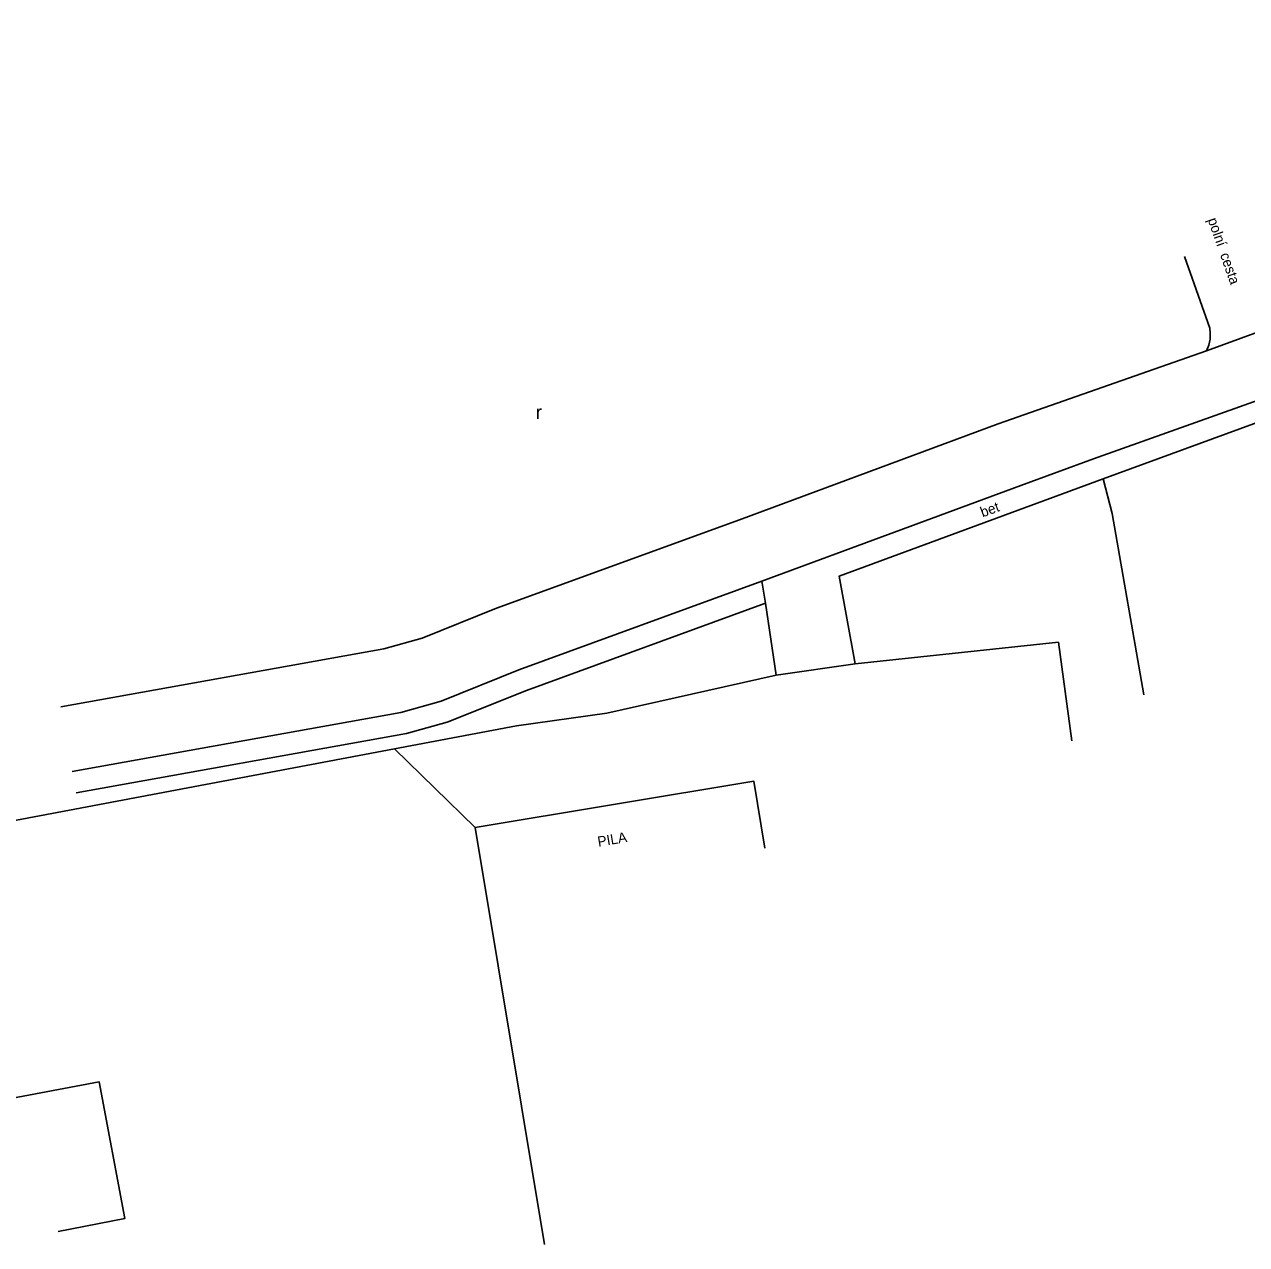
# Model space of a CAD drawing. Extents: x -544674 to -541478, y -1199076 to -1195527.
# Drawn here: x -542696.6 to -542606.7, y -1198958.2 to -1198868.4 of the extents above; entities that cross this region are included whole.
import ezdxf

# ---------------------------------------------------------------- set-up
doc = ezdxf.new("R2010")
doc.units = 0
for name, color, linetype in [('BUDOVY_MĚŘ', 7, 'Continuous'), ('POMOC_POPIS', 7, 'Continuous'), ('ROZHRANÍ_PLOCH', 7, 'Continuous'), ('ZN_DOPLŇKOVÉ', 7, 'Continuous'), ('ZN_KULTUR', 7, 'Continuous')]:
    doc.layers.add(name, color=color, linetype=linetype)

msp = doc.modelspace()

# ---------------------------------------------------------------- linework, layer by layer
at = {"layer": 'BUDOVY_MĚŘ'}
for points in [[(-542663.42, -1198927.53), (-542642.92, -1198924.11), (-542642.1, -1198929.04)], [(-542658.32, -1198958.2), (-542663.42, -1198927.53)], [(-542694.09, -1198957.23), (-542689.18, -1198956.28), (-542691.07, -1198946.23), (-542716.46, -1198951), (-542715.54, -1198955.91)]]:
    msp.add_lwpolyline(points, dxfattribs=at)
at = {"layer": 'ROZHRANÍ_PLOCH'}
for points in [[(-542527.8, -1198868.44), (-542528.3, -1198868.51), (-542529.54, -1198868.77), (-542530.76, -1198869.11), (-542531.26, -1198869.27), (-542565.34, -1198881.65), (-542617.93, -1198900.4), (-542623.29, -1198902.35), (-542642.32, -1198909.4)], [(-542611.23, -1198885.52), (-542609.38, -1198890.79), (-542609.34, -1198891.15), (-542609.36, -1198891.6), (-542609.45, -1198892.04), (-542609.63, -1198892.45)], [(-542609.63, -1198892.45), (-542601.96, -1198889.66)], [(-542693.91, -1198918.65), (-542670.14, -1198914.38), (-542667.32, -1198913.6), (-542661.84, -1198911.39), (-542643.98, -1198904.88), (-542624.95, -1198897.83), (-542609.63, -1198892.45)], [(-542617.21, -1198901.86), (-542636.64, -1198909.02), (-542635.46, -1198915.48)], [(-542642.32, -1198909.4), (-542660.2, -1198915.92), (-542665.93, -1198918.23), (-542668.89, -1198919.05), (-542693.06, -1198923.39)], [(-542642.07, -1198911.02), (-542642.32, -1198909.4)], [(-542642.07, -1198911.02), (-542659.65, -1198917.43), (-542665.47, -1198919.78), (-542668.47, -1198920.61), (-542692.78, -1198924.97)], [(-542641.27, -1198916.32), (-542642.07, -1198911.02)]]:
    msp.add_lwpolyline(points, dxfattribs=at)
at = {"layer": 'ZN_DOPLŇKOVÉ'}
for points in [[(-542617.21, -1198901.86), (-542601.14, -1198895.99), (-542585.1, -1198890.32), (-542564.95, -1198883.27)], [(-542617.21, -1198901.86), (-542616.56, -1198904.41)], [(-542614.24, -1198917.75), (-542616.56, -1198904.41)], [(-542635.46, -1198915.48), (-542620.51, -1198913.89), (-542619.52, -1198921.15)], [(-542635.46, -1198915.48), (-542641.27, -1198916.32)], [(-542669.35, -1198921.73), (-542660.39, -1198920.05), (-542653.74, -1198919.1), (-542641.27, -1198916.32)], [(-542703.3, -1198928.14), (-542669.35, -1198921.73)], [(-542663.42, -1198927.53), (-542669.35, -1198921.73)]]:
    msp.add_lwpolyline(points, dxfattribs=at)

# ---------------------------------------------------------------- texts
at = {"layer": 'POMOC_POPIS'}
for s, rotation, p in [('polní  cesta', 289.32999, (-542609.54, -1198882.8)), ('bet', 20.32001, (-542626.09, -1198904.71)), ('PILA', 9.47002, (-542654.35, -1198928.94))]:
    msp.add_text(s, height=0.75, rotation=rotation, dxfattribs=at).set_placement(p)
at = {"layer": 'ZN_KULTUR'}
msp.add_text('r', height=1, dxfattribs=at).set_placement((-542658.958, -1198897.462))

doc.saveas('drawing.dxf')
